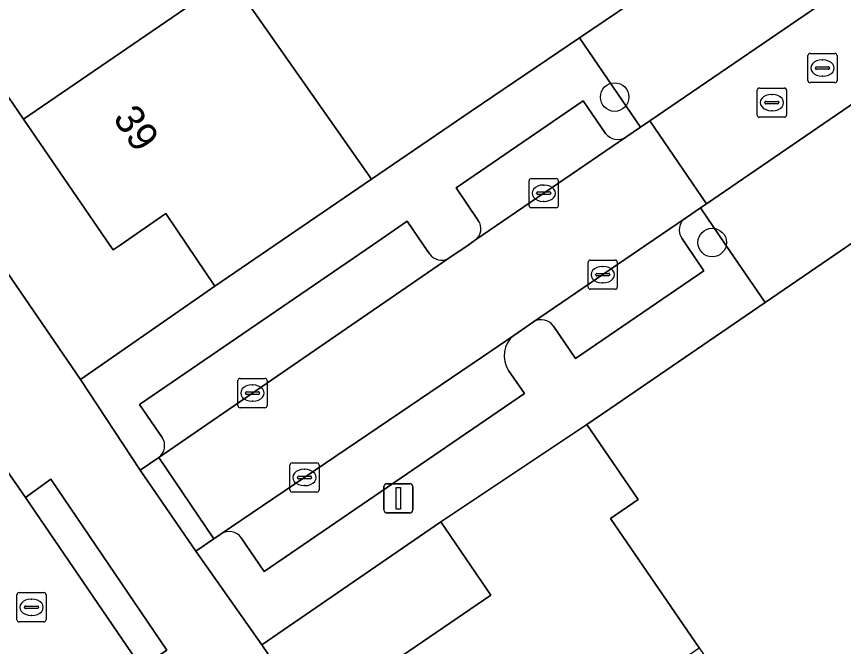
# Model space of a CAD drawing. Extents: x 157445 to 158888, y 383061 to 384688.
# Drawn here: x 158131.78 to 158160.1, y 383736.26 to 383757.82 of the extents above; entities that cross this region are included whole.
import ezdxf

# ---------------------------------------------------------------- set-up
doc = ezdxf.new("R2010")
doc.units = 0
for name, color, linetype in [('IMGEO_Boom', 7, 'Continuous'), ('IMGEO_Erf', 7, 'Continuous'), ('IMGEO_Kolk', 7, 'Continuous'), ('IMGEO_Lichtmast', 7, 'Continuous'), ('IMGEO_Muur', 7, 'Continuous'), ('IMGEO_Pand', 7, 'Continuous'), ('IMGEO_Pand_nummerreeks', 7, 'Continuous'), ('IMGEO_Parkeervlak_open', 7, 'Continuous'), ('IMGEO_Rijbaan_lokaal_open', 7, 'Continuous'), ('IMGEO_Rioolput', 7, 'Continuous'), ('IMGEO_Voetpad_open', 7, 'Continuous')]:
    doc.layers.add(name, color=color, linetype=linetype)

msp = doc.modelspace()

# ---------------------------------------------------------------- linework, layer by layer
at = {"layer": 'IMGEO_Boom'}
for centre in [(158152.265, 383755.066), (158155.606, 383750.086)]:
    msp.add_circle(centre, 0.489, dxfattribs=at)
at = {"layer": 'IMGEO_Erf'}
for points in [[(158100.07, 383794.919), (158133.967, 383745.394), (158138.577, 383748.596), (158137.627, 383750), (158136.894, 383751.084), (158135.326, 383750), (158135.086, 383749.834), (158134.972, 383750), (158132.021, 383754.315), (158128.922, 383758.845)], [(158129.893, 383772.619), (158132.984, 383768.099), (158136.324, 383770.384), (158139.341, 383765.973), (158136.001, 383763.688), (158139.1, 383759.157), (158143.934, 383752.254), (158147.354, 383754.586), (158151.062, 383757.099), (158153.24, 383758.575), (158155.492, 383760.102), (158153.838, 383762.522), (158151.56, 383760.967), (158149.428, 383764.089), (158151.705, 383765.644), (158151.465, 383765.99), (158149.209, 383764.425), (158148.434, 383765.542), (158150.797, 383767.157), (158147.667, 383771.669), (158144.621, 383776.06), (158141.5, 383780.559)], [(158174.823, 383729.666), (158172.674, 383732.789), (158175.207, 383734.532), (158173.142, 383737.56), (158170.609, 383735.817), (158168.593, 383738.747), (158166.445, 383741.869), (158168.978, 383743.612), (158166.832, 383746.303), (158164.686, 383744.832), (158162.59, 383747.892), (158164.736, 383749.362), (158163.021, 383751.865), (158157.421, 383748.033), (158152.1, 383744.39), (158151.309, 383743.861), (158153.074, 383741.289), (158152.122, 383740.636), (158155.162, 383736.206), (158158.274, 383731.67), (158161.393, 383727.123), (158164.503, 383722.59), (158167.678, 383717.963)]]:
    msp.add_lwpolyline(points, dxfattribs=at)
msp.add_lwpolyline([(158150.986, 383726.672), (158147.876, 383731.209), (158144.744, 383735.777), (158148.025, 383738.008), (158146.314, 383740.523), (158140.184, 383736.308), (158160.467, 383706.551), (158163.408, 383708.555), (158160.385, 383712.964), (158157.213, 383717.591), (158154.104, 383722.125)], close=True, dxfattribs=at)
at = {"layer": 'IMGEO_Kolk'}
for p, q in [((158157.225, 383755.376), (158158.077, 383755.376)), ((158157.15, 383754.45), (158157.15, 383755.302)), ((158157.638, 383755.156), (158157.663, 383755.156)), ((158158.151, 383755.302), (158158.151, 383754.45)), ((158157.409, 383754.87), (158157.409, 383754.882)), ((158157.847, 383754.833), (158157.449, 383754.833)), ((158157.452, 383754.919), (158157.85, 383754.919)), ((158157.893, 383754.882), (158157.893, 383754.87)), ((158157.661, 383754.596), (158157.636, 383754.596)), ((158158.077, 383754.376), (158157.225, 383754.376)), ((158149.41, 383752.274), (158150.262, 383752.274)), ((158149.335, 383751.348), (158149.335, 383752.2)), ((158149.823, 383752.054), (158149.848, 383752.054)), ((158150.336, 383752.2), (158150.336, 383751.348)), ((158149.594, 383751.768), (158149.594, 383751.78)), ((158150.032, 383751.731), (158149.634, 383751.731)), ((158149.637, 383751.817), (158150.035, 383751.817)), ((158150.078, 383751.78), (158150.078, 383751.768)), ((158149.846, 383751.494), (158149.821, 383751.494)), ((158150.262, 383751.274), (158149.41, 383751.274)), ((158151.355, 383748.56), (158151.355, 383749.412)), ((158151.43, 383749.486), (158152.282, 383749.486)), ((158152.356, 383749.412), (158152.356, 383748.56)), ((158151.843, 383749.266), (158151.868, 383749.266)), ((158151.614, 383748.98), (158151.614, 383748.992)), ((158152.052, 383748.943), (158151.654, 383748.943)), ((158151.657, 383749.029), (158152.055, 383749.029)), ((158152.098, 383748.992), (158152.098, 383748.98)), ((158151.866, 383748.706), (158151.841, 383748.706)), ((158152.282, 383748.486), (158151.43, 383748.486)), ((158139.36, 383744.505), (158139.36, 383745.357)), ((158139.435, 383745.431), (158140.287, 383745.431)), ((158139.848, 383745.211), (158139.873, 383745.211)), ((158140.361, 383745.357), (158140.361, 383744.505)), ((158139.619, 383744.925), (158139.619, 383744.937)), ((158140.057, 383744.888), (158139.659, 383744.888)), ((158139.662, 383744.974), (158140.06, 383744.974)), ((158140.103, 383744.937), (158140.103, 383744.925)), ((158139.871, 383744.651), (158139.846, 383744.651)), ((158140.287, 383744.431), (158139.435, 383744.431)), ((158141.143, 383741.617), (158141.143, 383742.469)), ((158141.218, 383742.543), (158142.07, 383742.543)), ((158142.144, 383742.469), (158142.144, 383741.617)), ((158141.402, 383742.037), (158141.402, 383742.049)), ((158141.445, 383742.086), (158141.843, 383742.086)), ((158141.631, 383742.323), (158141.656, 383742.323)), ((158141.886, 383742.049), (158141.886, 383742.037)), ((158141.84, 383742), (158141.442, 383742)), ((158141.654, 383741.763), (158141.629, 383741.763)), ((158142.07, 383741.543), (158141.218, 383741.543))]:
    msp.add_line(p, q, dxfattribs=at)
for points in [[(158157.225, 383755.376), (158158.077, 383755.376)], [(158157.15, 383754.45), (158157.15, 383755.302)], [(158158.151, 383755.302), (158158.151, 383754.45)], [(158158.077, 383754.376), (158157.225, 383754.376)], [(158149.41, 383752.274), (158150.262, 383752.274)], [(158149.335, 383751.348), (158149.335, 383752.2)], [(158150.336, 383752.2), (158150.336, 383751.348)], [(158150.262, 383751.274), (158149.41, 383751.274)], [(158151.355, 383748.56), (158151.355, 383749.412)], [(158151.43, 383749.486), (158152.282, 383749.486)], [(158152.356, 383749.412), (158152.356, 383748.56)], [(158152.282, 383748.486), (158151.43, 383748.486)], [(158139.36, 383744.505), (158139.36, 383745.357)], [(158139.435, 383745.431), (158140.287, 383745.431)], [(158140.361, 383745.357), (158140.361, 383744.505)], [(158140.287, 383744.431), (158139.435, 383744.431)], [(158141.143, 383741.617), (158141.143, 383742.469)], [(158141.218, 383742.543), (158142.07, 383742.543)], [(158142.144, 383742.469), (158142.144, 383741.617)], [(158142.07, 383741.543), (158141.218, 383741.543)]]:
    msp.add_lwpolyline(points, dxfattribs=at)
for centre, radius, start, end in [((158157.227, 383755.3), 0.0765, 91.552, 178.448), ((158157.227, 383755.3), 0.0765, 91.552, 178.448), ((158158.075, 383755.3), 0.0765, 1.552, 88.448), ((158158.075, 383755.3), 0.0765, 1.552, 88.448), ((158157.449, 383754.879), 0.0403, 85.8775, 175.7526), ((158157.446, 383754.869), 0.0366, 178.938, 274.7102), ((158157.85, 383754.876), 0.043, 264.8664, 352.4533), ((158157.854, 383754.881), 0.0386, 1.7309, 96.639), ((158157.227, 383754.452), 0.0765, 181.552, 268.448), ((158157.227, 383754.452), 0.0765, 181.552, 268.448), ((158158.075, 383754.452), 0.0765, 271.552, 358.448), ((158158.075, 383754.452), 0.0765, 271.552, 358.448), ((158149.412, 383752.198), 0.0765, 91.552, 178.448), ((158149.412, 383752.198), 0.0765, 91.552, 178.448), ((158150.26, 383752.198), 0.0765, 1.552, 88.448), ((158150.26, 383752.198), 0.0765, 1.552, 88.448), ((158149.634, 383751.777), 0.0403, 85.8775, 175.7526), ((158149.631, 383751.767), 0.0366, 178.938, 274.7102), ((158150.035, 383751.774), 0.043, 264.8664, 352.4533), ((158150.039, 383751.779), 0.0386, 1.7309, 96.639), ((158149.412, 383751.35), 0.0765, 181.552, 268.448), ((158149.412, 383751.35), 0.0765, 181.552, 268.448), ((158150.26, 383751.35), 0.0765, 271.552, 358.448), ((158150.26, 383751.35), 0.0765, 271.552, 358.448), ((158151.432, 383749.41), 0.0765, 91.552, 178.448), ((158151.432, 383749.41), 0.0765, 91.552, 178.448), ((158152.28, 383749.41), 0.0765, 1.552, 88.448), ((158152.28, 383749.41), 0.0765, 1.552, 88.448), ((158151.654, 383748.989), 0.0403, 85.8775, 175.7526), ((158151.651, 383748.979), 0.0366, 178.938, 274.7102), ((158152.055, 383748.986), 0.043, 264.8664, 352.4533), ((158152.059, 383748.991), 0.0386, 1.7309, 96.639), ((158151.432, 383748.562), 0.0765, 181.552, 268.448), ((158151.432, 383748.562), 0.0765, 181.552, 268.448), ((158152.28, 383748.562), 0.0765, 271.552, 358.448), ((158152.28, 383748.562), 0.0765, 271.552, 358.448), ((158139.437, 383745.355), 0.0765, 91.552, 178.448), ((158139.437, 383745.355), 0.0765, 91.552, 178.448), ((158140.285, 383745.355), 0.0765, 1.552, 88.448), ((158140.285, 383745.355), 0.0765, 1.552, 88.448), ((158139.659, 383744.934), 0.0403, 85.8775, 175.7526), ((158139.656, 383744.924), 0.0366, 178.938, 274.7102), ((158140.06, 383744.931), 0.043, 264.8664, 352.4533), ((158140.064, 383744.936), 0.0386, 1.7309, 96.639), ((158139.437, 383744.507), 0.0765, 181.552, 268.448), ((158139.437, 383744.507), 0.0765, 181.552, 268.448), ((158140.285, 383744.507), 0.0765, 271.552, 358.448), ((158140.285, 383744.507), 0.0765, 271.552, 358.448), ((158141.22, 383742.467), 0.0765, 91.552, 178.448), ((158141.22, 383742.467), 0.0765, 91.552, 178.448), ((158142.068, 383742.467), 0.0765, 1.552, 88.448), ((158142.068, 383742.467), 0.0765, 1.552, 88.448), ((158141.442, 383742.046), 0.0403, 85.8775, 175.7526), ((158141.847, 383742.048), 0.0386, 1.7309, 96.639), ((158141.439, 383742.036), 0.0366, 178.938, 274.7102), ((158141.843, 383742.043), 0.043, 264.8664, 352.4533), ((158141.22, 383741.619), 0.0765, 181.552, 268.448), ((158141.22, 383741.619), 0.0765, 181.552, 268.448), ((158142.068, 383741.619), 0.0765, 271.552, 358.448), ((158142.068, 383741.619), 0.0765, 271.552, 358.448)]:
    msp.add_arc(centre, radius, start, end, dxfattribs=at)
for centre, major_axis, ratio, start_param, end_param in [((158157.637, 383754.876), (-0.387, 0.002), 0.722429, 4.712389, 7.853982), ((158157.662, 383754.876), (-0.39, 0.002), 0.717154, 1.570796, 4.712389), ((158149.822, 383751.774), (-0.387, 0.002), 0.722429, 4.712389, 7.853982), ((158149.847, 383751.774), (-0.39, 0.002), 0.717154, 1.570796, 4.712389), ((158151.842, 383748.986), (-0.387, 0.002), 0.722429, 4.712389, 7.853982), ((158151.867, 383748.986), (-0.39, 0.002), 0.717154, 1.570796, 4.712389), ((158139.847, 383744.931), (-0.387, 0.002), 0.722429, 4.712389, 7.853982), ((158139.872, 383744.931), (-0.39, 0.002), 0.717154, 1.570796, 4.712389), ((158141.63, 383742.043), (-0.387, 0.002), 0.722429, 4.712389, 7.853982), ((158141.655, 383742.043), (-0.39, 0.002), 0.717154, 1.570796, 4.712389)]:
    msp.add_ellipse(centre, major_axis=major_axis, ratio=ratio, start_param=start_param, end_param=end_param, dxfattribs=at)
at = {"layer": 'IMGEO_Lichtmast'}
for p, q in [((158144.46, 383741.829), (158145.25, 383741.829)), ((158145.25, 383741.829), (158144.46, 383741.829)), ((158144.36, 383740.929), (158144.36, 383741.729)), ((158144.36, 383741.729), (158144.36, 383740.929)), ((158145.35, 383741.729), (158145.35, 383740.929)), ((158145.35, 383740.929), (158145.35, 383741.729)), ((158145.25, 383740.829), (158144.46, 383740.829)), ((158144.46, 383740.829), (158145.25, 383740.829))]:
    msp.add_line(p, q, dxfattribs=at)
msp.add_lwpolyline([(158144.78, 383741.704), (158144.93, 383741.704), (158144.93, 383740.954), (158144.78, 383740.954), (158144.78, 383741.704)], dxfattribs=at)
for centre, start, end in [((158144.46, 383741.729), 90, 180), ((158144.46, 383741.729), 90, 180), ((158145.25, 383741.729), 0, 90), ((158145.25, 383741.729), 360, 90), ((158144.46, 383740.929), 180, 270), ((158144.46, 383740.929), 180, 270), ((158145.25, 383740.929), 270, 0), ((158145.25, 383740.929), 270, 0)]:
    msp.add_arc(centre, 0.1, start, end, dxfattribs=at)
at = {"layer": 'IMGEO_Muur'}
for points in [[(158157.421, 383748.033), (158163.021, 383751.865)], [(158152.1, 383744.39), (158157.421, 383748.033)]]:
    msp.add_lwpolyline(points, dxfattribs=at)
at = {"layer": 'IMGEO_Pand'}
for points in [[(158132.021, 383754.315), (158139.1, 383759.157), (158136.001, 383763.688), (158128.922, 383758.845)], [(158139.1, 383759.157), (158132.021, 383754.315), (158134.972, 383750), (158135.086, 383749.834), (158135.326, 383750), (158136.894, 383751.084), (158137.627, 383750), (158138.577, 383748.596), (158140.625, 383750), (158143.934, 383752.254)], [(158152.122, 383740.636), (158153.074, 383741.289), (158151.309, 383743.861), (158146.314, 383740.523), (158148.025, 383738.008), (158144.744, 383735.777), (158147.876, 383731.209), (158155.162, 383736.206)]]:
    msp.add_lwpolyline(points, close=True, dxfattribs=at)
at = {"layer": 'IMGEO_Parkeervlak_open'}
for points in [[(158151.951, 383753.824), (158151.191, 383754.937), (158146.834, 383751.958), (158147.596, 383750.843)], [(158147.501, 383750.176), (158152.646, 383753.693)], [(158154.689, 383750.924), (158153.338, 383750), (158149.491, 383747.37)], [(158145.925, 383749.7), (158145.72, 383750), (158145.163, 383750.815), (158143.971, 383750), (158135.993, 383744.545), (158136.767, 383743.412)], [(158150.166, 383747.226), (158150.927, 383746.112), (158155.323, 383749.117), (158154.72, 383750), (158154.562, 383750.231)], [(158136.657, 383742.731), (158146.587, 383749.548)], [(158148.813, 383746.907), (158147.744, 383746.176), (158138.788, 383740.11)], [(158139.476, 383739.975), (158140.263, 383738.822), (158149.173, 383744.914), (158148.635, 383745.702)]]:
    msp.add_lwpolyline(points, dxfattribs=at)
for centre, radius, start, end in [((158152.371, 383754.144), 0.528, 217.2771, 301.3741), ((158147.184, 383750.561), 0.499, 309.4487, 34.3392), ((158154.972, 383750.514), 0.498, 124.6121, 214.6182), ((158146.338, 383749.98), 0.499, 214.174, 299.9633), ((158149.753, 383746.943), 0.501, 34.3725, 121.5424), ((158149.375, 383746.208), 0.897, 128.8251, 214.3692), ((158136.353, 383743.129), 0.501, 307.301, 34.3479), ((158139.063, 383739.692), 0.501, 34.4419, 123.3549)]:
    msp.add_arc(centre, radius, start, end, dxfattribs=at)
at = {"layer": 'IMGEO_Rijbaan_lokaal_open'}
for points in [[(158165.587, 383758.374), (158163.604, 383761.185), (158153.468, 383754.255), (158155.41, 383751.416)], [(158154.689, 383750.924), (158155.205, 383751.276), (158155.41, 383751.416), (158153.468, 383754.255), (158153.152, 383754.039), (158152.646, 383753.693), (158147.501, 383750.176), (158147.245, 383750), (158146.587, 383749.548), (158136.657, 383742.731), (158138.533, 383739.937), (158138.788, 383740.11), (158147.744, 383746.176), (158148.813, 383746.907), (158149.491, 383747.37), (158153.338, 383750)], [(158124.947, 383743.707), (158136.966, 383725.919), (158137.06, 383725.779), (158139.014, 383722.977), (158143.805, 383715.982), (158145.717, 383713.22), (158149.667, 383707.427), (158151.552, 383704.597), (158152.591, 383703.163), (158156.428, 383705.77), (158139.617, 383730.272), (158139.182, 383730.933), (158137.076, 383734.051), (158136.056, 383735.537), (158132.093, 383741.351), (158130.874, 383743.091), (158128.732, 383746.298)], [(158136.012, 383742.288), (158137.923, 383739.524), (158138.533, 383739.937), (158136.657, 383742.731)]]:
    msp.add_lwpolyline(points, close=True, dxfattribs=at)
at = {"layer": 'IMGEO_Rioolput'}
for p, q in [((158158.884, 383755.633), (158158.884, 383756.485)), ((158158.959, 383756.559), (158159.811, 383756.559)), ((158159.885, 383756.485), (158159.885, 383755.633)), ((158159.372, 383756.339), (158159.397, 383756.339)), ((158159.143, 383756.053), (158159.143, 383756.065)), ((158159.581, 383756.016), (158159.183, 383756.016)), ((158159.186, 383756.102), (158159.584, 383756.102)), ((158159.627, 383756.065), (158159.627, 383756.053)), ((158159.395, 383755.779), (158159.37, 383755.779)), ((158159.811, 383755.559), (158158.959, 383755.559)), ((158131.869, 383738.099), (158132.721, 383738.099)), ((158131.794, 383737.173), (158131.794, 383738.025)), ((158132.282, 383737.879), (158132.307, 383737.879)), ((158132.795, 383738.025), (158132.795, 383737.173)), ((158132.053, 383737.593), (158132.053, 383737.605)), ((158132.491, 383737.556), (158132.093, 383737.556)), ((158132.096, 383737.642), (158132.494, 383737.642)), ((158132.537, 383737.605), (158132.537, 383737.593)), ((158132.305, 383737.319), (158132.28, 383737.319)), ((158132.721, 383737.099), (158131.869, 383737.099))]:
    msp.add_line(p, q, dxfattribs=at)
for points in [[(158158.884, 383755.633), (158158.884, 383756.485)], [(158158.959, 383756.559), (158159.811, 383756.559)], [(158159.885, 383756.485), (158159.885, 383755.633)], [(158159.811, 383755.559), (158158.959, 383755.559)], [(158131.869, 383738.099), (158132.721, 383738.099)], [(158131.794, 383737.173), (158131.794, 383738.025)], [(158132.795, 383738.025), (158132.795, 383737.173)], [(158132.721, 383737.099), (158131.869, 383737.099)]]:
    msp.add_lwpolyline(points, dxfattribs=at)
for centre, radius, start, end in [((158158.961, 383756.483), 0.0765, 91.552, 178.448), ((158158.961, 383756.483), 0.0765, 91.552, 178.448), ((158159.809, 383756.483), 0.0765, 1.552, 88.448), ((158159.809, 383756.483), 0.0765, 1.552, 88.448), ((158159.183, 383756.062), 0.0403, 85.8775, 175.7526), ((158159.18, 383756.052), 0.0366, 178.938, 274.7102), ((158159.584, 383756.059), 0.043, 264.8664, 352.4533), ((158159.588, 383756.064), 0.0386, 1.7309, 96.639), ((158158.961, 383755.635), 0.0765, 181.552, 268.448), ((158158.961, 383755.635), 0.0765, 181.552, 268.448), ((158159.809, 383755.635), 0.0765, 271.552, 358.448), ((158159.809, 383755.635), 0.0765, 271.552, 358.448), ((158131.871, 383738.023), 0.0765, 91.552, 178.448), ((158131.871, 383738.023), 0.0765, 91.552, 178.448), ((158132.719, 383738.023), 0.0765, 1.552, 88.448), ((158132.719, 383738.023), 0.0765, 1.552, 88.448), ((158132.093, 383737.602), 0.0403, 85.8775, 175.7526), ((158132.09, 383737.592), 0.0366, 178.938, 274.7102), ((158132.494, 383737.599), 0.043, 264.8664, 352.4533), ((158132.498, 383737.604), 0.0386, 1.7309, 96.639), ((158131.871, 383737.175), 0.0765, 181.552, 268.448), ((158131.871, 383737.175), 0.0765, 181.552, 268.448), ((158132.719, 383737.175), 0.0765, 271.552, 358.448), ((158132.719, 383737.175), 0.0765, 271.552, 358.448)]:
    msp.add_arc(centre, radius, start, end, dxfattribs=at)
for centre, major_axis, ratio, start_param, end_param in [((158159.371, 383756.059), (-0.387, 0.002), 0.722429, 4.712389, 7.853982), ((158159.396, 383756.059), (-0.39, 0.002), 0.717154, 1.570796, 4.712389), ((158132.281, 383737.599), (-0.387, 0.002), 0.722429, 4.712389, 7.853982), ((158132.306, 383737.599), (-0.39, 0.002), 0.717154, 1.570796, 4.712389)]:
    msp.add_ellipse(centre, major_axis=major_axis, ratio=ratio, start_param=start_param, end_param=end_param, dxfattribs=at)
at = {"layer": 'IMGEO_Voetpad_open'}
for points in [[(158179.736, 383678.736), (158176.861, 383682.64), (158173.87, 383686.963), (158169.122, 383693.946), (158167.439, 383696.302), (158162.788, 383703.146), (158161.262, 383705.385), (158160.467, 383706.551), (158140.184, 383736.308), (158137.923, 383739.524), (158136.012, 383742.288), (158133.967, 383745.394), (158100.07, 383794.919), (158099.197, 383796.194), (158087.818, 383812.82), (158068.445, 383841.037), (158067.539, 383842.357), (158067.092, 383843.008), (158064.14, 383847.309)], [(158167.014, 383759.349), (158165.587, 383758.374), (158155.41, 383751.416), (158155.205, 383751.276), (158156.077, 383750), (158157.421, 383748.033), (158163.021, 383751.865), (158164.227, 383752.691), (158164.262, 383752.715), (158166.506, 383754.251)], [(158152.646, 383753.693), (158153.152, 383754.039), (158151.062, 383757.099), (158147.354, 383754.586), (158143.934, 383752.254), (158140.625, 383750), (158138.577, 383748.596), (158133.967, 383745.394), (158136.012, 383742.288), (158136.657, 383742.731)], [(158147.596, 383750.843), (158146.834, 383751.958), (158151.191, 383754.937), (158151.951, 383753.824)], [(158157.421, 383748.033), (158156.077, 383750), (158155.205, 383751.276), (158154.689, 383750.924)], [(158143.971, 383750), (158145.163, 383750.815), (158145.72, 383750), (158145.925, 383749.7)], [(158136.767, 383743.412), (158135.993, 383744.545), (158143.971, 383750)], [(158146.587, 383749.548), (158147.245, 383750), (158147.501, 383750.176)], [(158154.562, 383750.231), (158154.72, 383750), (158155.323, 383749.117), (158150.927, 383746.112), (158150.166, 383747.226)], [(158138.788, 383740.11), (158138.533, 383739.937), (158137.923, 383739.524), (158140.184, 383736.308), (158146.314, 383740.523), (158151.309, 383743.861), (158152.1, 383744.39), (158157.421, 383748.033)], [(158128.157, 383747.162), (158128.732, 383746.298), (158130.874, 383743.091), (158132.093, 383741.351), (158132.961, 383741.981), (158136.927, 383736.134), (158136.056, 383735.537), (158137.076, 383734.051), (158139.182, 383730.933), (158139.617, 383730.272)], [(158149.491, 383747.37), (158148.813, 383746.907)], [(158148.635, 383745.702), (158149.173, 383744.914), (158140.263, 383738.822), (158139.476, 383739.975)]]:
    msp.add_lwpolyline(points, dxfattribs=at)
for points in [[(158163.604, 383761.185), (158162.561, 383762.71), (158161.541, 383764.202), (158156.467, 383760.763), (158155.492, 383760.102), (158153.24, 383758.575), (158151.062, 383757.099), (158153.152, 383754.039), (158153.468, 383754.255)], [(158132.093, 383741.351), (158136.056, 383735.537), (158136.927, 383736.134), (158132.961, 383741.981)]]:
    msp.add_lwpolyline(points, close=True, dxfattribs=at)
for centre, radius, start, end in [((158152.371, 383754.144), 0.528, 217.2771, 301.3741), ((158147.184, 383750.561), 0.499, 309.4487, 34.3392), ((158154.972, 383750.514), 0.498, 124.6121, 214.6182), ((158146.338, 383749.98), 0.499, 214.174, 299.9633), ((158149.753, 383746.943), 0.501, 34.3725, 121.5424), ((158149.375, 383746.208), 0.897, 128.8251, 214.3692), ((158136.353, 383743.129), 0.501, 307.301, 34.3479), ((158139.063, 383739.692), 0.501, 34.4419, 123.3549)]:
    msp.add_arc(centre, radius, start, end, dxfattribs=at)

# ---------------------------------------------------------------- texts
at = {"layer": 'IMGEO_Pand_nummerreeks'}
msp.add_text('39', height=1, rotation=304.3715, dxfattribs=at).set_placement((158135.057, 383754.341))

doc.saveas('drawing.dxf')
